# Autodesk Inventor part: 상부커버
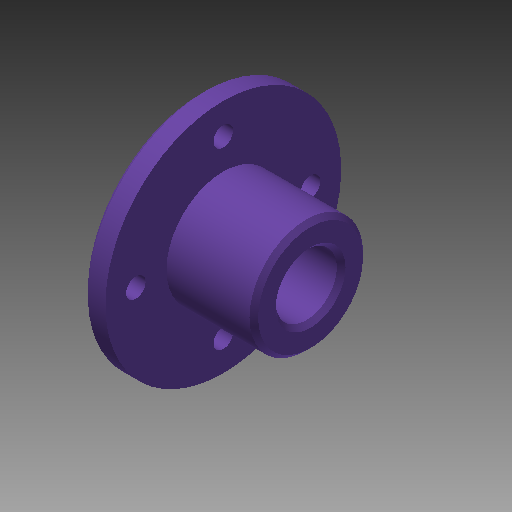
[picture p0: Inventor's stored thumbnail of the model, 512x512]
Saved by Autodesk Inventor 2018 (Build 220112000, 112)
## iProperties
Created: 2015-09
Part Number: 상부커버
Material: 알루미늄 6061
Document SubType Name: Modeling
Designer: mduedu
Density: 1 g/cm^3
Appearance: 보라색
Author: mduedu
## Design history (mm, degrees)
sketch "스케치1"
  geometry: L1 (-12.5, 0)-(12.5, 0); L2 (-12.5, 0)-(-12.5, 27); L3 (-12.5, 27)-(-7.5, 27); L4 (-7.5, 27)-(-7.5, 13); L5 (-7.5, 13)-(12.5, 13); L6 (12.5, 13)-(12.5, 0); 2 further points
  constraints: 12 end point, 2 parallel, 2 perpendicular, 1 coincident, 1 horizontal, 1 midpoint, 1 vertical
  dimensions: "d0" = 25 distance of L1.start L1.end; "d2" = 5 distance of L2.end L3.end; "d3" = 26 diameter of L5 L1; "d4" = 54 diameter of L3 L1
revolve "회전1" sketch "스케치1" stored, may be unused: angle "d5" = 90 deg
hole "구멍1" diameter "d8" = 14; stored, may be unused: countersink angle "d12" = 90 deg, drill point angle "d14" = 118 deg; dims "d6" = 10, "d7" = 10, "d9" = 6, "d10" = 4, "d11" = 2, "d13" = 8
chamfer "모따기1" distance "d15" = 1; stored, may be unused: second distance "d16" = 2, angle "d17" = 45 deg
chamfer "모따기2" distance "d18" = 1; stored, may be unused: second distance "d19" = 2, angle "d20" = 45 deg
sketch "스케치2" dims "d21" = 40
  geometry: 6 further points
  constraints: 2 vertical alignment, 1 coincident, 7 other
  dimensions: "d25" = 360 deg dimension on point (0, 0) point (0, 20) (derived)
sketch "스케치3"
  geometry: 4 further points
hole "구멍2" sketch "스케치3" at (0, 20), (-20, 0), (20, 0), (0, -20) diameter "d27" = 4.5; stored, may be unused: countersink angle "d31" = 90 deg, drill point angle "d33" = 0 deg; dims "d28" = 6, "d29" = 4, "d30" = 2, "d32" = 8
chamfer "모따기3" distance "d34" = 1; stored, may be unused: second distance "d35" = 2, angle "d36" = 45 deg
node "솔리드1"
